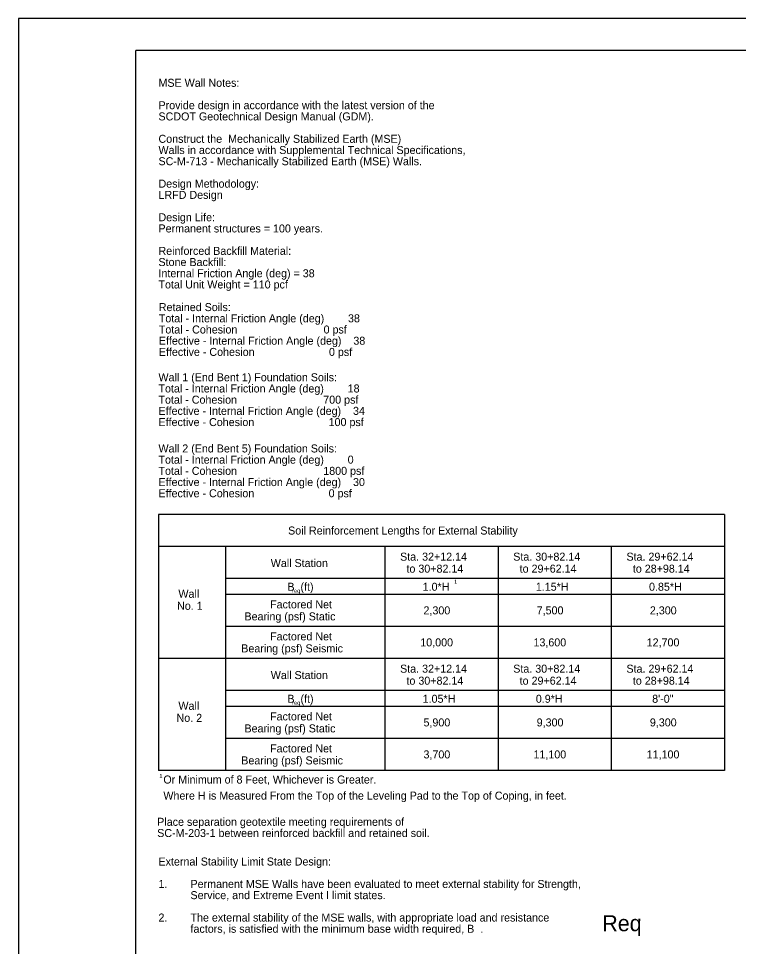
# Model space of a CAD drawing. Extents: x 96 to 240, y 601 to 689.
# Drawn here: x 95.8 to 140.8, y 631 to 689 of the extents above; entities that cross this region are included whole.
import ezdxf

# ---------------------------------------------------------------- set-up
doc = ezdxf.new("R2010")
doc.units = 0
for name, color, linetype in [('BR_BORDER LINES', 7, 'Continuous'), ('BR_TABLE LINES', 7, 'Continuous'), ('BR_TEXT', 7, 'Continuous'), ('Level 31', 7, 'Continuous')]:
    doc.layers.add(name, color=color, linetype=linetype)

msp = doc.modelspace()

# ---------------------------------------------------------------- linework, layer by layer
at = {"layer": 'BR_BORDER LINES'}
for p in [(237.837, 687.003), (103.173, 603.003)]:
    msp.add_line(p, (103.173, 687.003), dxfattribs=at)
at = {"layer": 'BR_TABLE LINES'}
for p, q in [((139.93, 658.013), (104.579, 658.013)), ((104.579, 658.013), (104.579, 642.013)), ((139.93, 658.013), (139.93, 642.013)), ((139.93, 656.013), (104.579, 656.013)), ((108.755, 656.013), (108.755, 642.013)), ((118.72, 656.013), (118.72, 642.013)), ((125.79, 656.013), (125.79, 642.013)), ((132.86, 656.013), (132.86, 642.013)), ((139.93, 654.013), (108.755, 654.013)), ((139.93, 653.013), (108.755, 653.013)), ((139.93, 651.013), (108.755, 651.013)), ((139.93, 649.013), (104.579, 649.013)), ((139.93, 647.013), (108.755, 647.013)), ((139.93, 646.013), (108.755, 646.013)), ((139.93, 644.013), (108.755, 644.013)), ((139.93, 642.013), (104.579, 642.013))]:
    msp.add_line(p, q, dxfattribs=at)
at = {"layer": 'Level 31'}
msp.add_lwpolyline([(95.84, 601.004), (239.84, 601.004), (239.84, 689.004), (95.84, 689.004)], close=True, dxfattribs=at)

# ---------------------------------------------------------------- texts
at = {"layer": 'BR_TEXT'}
for s, height, p in [('MSE Wall Notes:', 0.5, (104.579, 684.739)), ('Provide design in accordance with the latest version of the ', 0.5, (104.579, 683.339)), ('SCDOT Geotechnical Design Manual (GDM). ', 0.5, (104.579, 682.639)), ('Construct the  Mechanically Stabilized Earth (MSE) ', 0.5, (104.579, 681.239)), ('Walls in accordance with Supplemental Technical Specifications,', 0.5, (104.579, 680.539)), ('SC-M-713 - Mechanically Stabilized Earth (MSE) Walls.', 0.5, (104.579, 679.839)), ('Design Methodology:', 0.5, (104.579, 678.439)), ('LRFD Design', 0.5, (104.579, 677.739)), ('Design Life:', 0.5, (104.579, 676.339)), ('Permanent structures = 100 years.', 0.5, (104.579, 675.639)), ('Reinforced Backfill Material:', 0.5, (104.579, 674.239)), ('Stone Backfill:', 0.5, (104.579, 673.539)), ('Internal Friction Angle (deg) = 38', 0.5, (104.579, 672.839)), ('Total Unit Weight = 110 pcf', 0.5, (104.579, 672.139)), ('Retained Soils:', 0.5, (104.6, 670.724)), ('Total - Internal Friction Angle (deg)        38', 0.5, (104.6, 670.024)), ('Total - Cohesion                             0 psf', 0.5, (104.6, 669.324)), ('Effective - Internal Friction Angle (deg)    38', 0.5, (104.6, 668.624)), ('Effective - Cohesion                         0 psf', 0.5, (104.6, 667.924)), ('Wall 1 (End Bent 1) Foundation Soils:', 0.5, (104.579, 666.34)), ('Total - Internal Friction Angle (deg)        18', 0.5, (104.579, 665.64)), ('Total - Cohesion                             700 psf', 0.5, (104.579, 664.94)), ('Effective - Internal Friction Angle (deg)    34', 0.5, (104.579, 664.24)), ('Effective - Cohesion                         100 psf', 0.5, (104.579, 663.54)), ('Wall 2 (End Bent 5) Foundation Soils:', 0.5, (104.579, 661.892)), ('Total - Internal Friction Angle (deg)        0', 0.5, (104.579, 661.192)), ('Total - Cohesion                             1800 psf', 0.5, (104.579, 660.492)), ('Effective - Internal Friction Angle (deg)    30', 0.5, (104.579, 659.792)), ('Effective - Cohesion                         0 psf', 0.5, (104.579, 659.092)), ('Place separation geotextile meeting requirements of ', 0.5, (104.499, 638.562)), ('SC-M-203-1 between reinforced backfill and retained soil.', 0.5, (104.499, 637.862)), ('External Stability Limit State Design:', 0.5, (104.579, 636.081)), ('1.', 0.5, (104.579, 634.681)), ('Permanent MSE Walls have been evaluated to meet external stability for Strength,', 0.5, (106.579, 634.681)), ('Service, and Extreme Event I limit states.', 0.5, (106.579, 633.981)), ('2.', 0.5, (104.579, 632.581)), ('The external stability of the MSE walls, with appropriate load and resistance', 0.5, (106.579, 632.581)), ('          Req', 1, (128.587, 631.976)), ('factors, is satisfied with the minimum base width required, B  .', 0.5, (106.579, 631.881))]:
    msp.add_text(s, height=height, dxfattribs=at).set_placement(p)
for s, height, p in [('Soil Reinforcement Lengths for External Stability', 0.5, (112.677, 656.763)), ('Wall Station', 0.5, (111.592, 654.731)), ('Sta. 32+12.14 ', 0.5, (119.669, 655.131)), ('Sta. 30+82.14', 0.5, (126.739, 655.131)), ('Sta. 29+62.14', 0.5, (133.809, 655.131)), ('to 30+82.14', 0.5, (120.069, 654.381)), ('to 29+62.14', 0.5, (127.139, 654.381)), ('to 28+98.14', 0.5, (134.209, 654.381)), ('B  (ft)', 0.5, (112.631, 653.251)), ('1.0*H', 0.5, (121.079, 653.251)), ('1', 0.25, (123.044, 653.69)), ('1.15*H', 0.5, (128.149, 653.251)), ('0.85*H', 0.5, (135.219, 653.251)), ('Wall', 0.5, (105.824, 652.81)), ('req', 0.25, (112.933, 653.126)), ('No. 1', 0.5, (105.741, 652.06)), ('Factored Net', 0.5, (111.551, 652.149)), ('2,300', 0.5, (121.132, 651.774)), ('7,500', 0.5, (128.202, 651.774)), ('2,300', 0.5, (135.272, 651.774)), ('Bearing (psf) Static', 0.5, (109.95, 651.399)), ('Factored Net', 0.5, (111.551, 650.149)), ('10,000', 0.5, (120.932, 649.774)), ('13,600', 0.5, (128.002, 649.774)), ('12,700', 0.5, (135.072, 649.774)), ('Bearing (psf) Seismic', 0.5, (109.75, 649.399)), ('Wall Station', 0.5, (111.592, 647.731)), ('Sta. 32+12.14 ', 0.5, (119.669, 648.131)), ('Sta. 30+82.14', 0.5, (126.739, 648.131)), ('Sta. 29+62.14', 0.5, (133.809, 648.131)), ('to 30+82.14', 0.5, (120.069, 647.381)), ('to 29+62.14', 0.5, (127.139, 647.381)), ('to 28+98.14', 0.5, (134.209, 647.381)), ('B  (ft)', 0.5, (112.631, 646.251)), ('1.05*H', 0.5, (121.079, 646.251)), ('0.9*H', 0.5, (128.149, 646.251)), ('8\'-0"', 0.5, (135.416, 646.251)), ('Wall', 0.5, (105.824, 645.81)), ('req', 0.25, (112.933, 646.126)), ('No. 2', 0.5, (105.707, 645.06)), ('Factored Net', 0.5, (111.551, 645.149)), ('Bearing (psf) Static', 0.5, (109.95, 644.399)), ('5,900', 0.5, (121.132, 644.774)), ('9,300', 0.5, (128.202, 644.774)), ('9,300', 0.5, (135.272, 644.774)), ('Factored Net', 0.5, (111.551, 643.149)), ('3,700', 0.5, (121.132, 642.774)), ('11,100', 0.5, (128.002, 642.774)), ('11,100', 0.5, (135.072, 642.774)), ('Bearing (psf) Seismic', 0.5, (109.75, 642.399)), ('1', 0.25, (104.637, 641.542)), ('Or Minimum of 8 Feet, Whichever is Greater.', 0.5, (104.885, 641.204)), ('Where H is Measured From the Top of the Leveling Pad to the Top of Coping, in feet.', 0.5, (104.885, 640.2))]:
    msp.add_text(s, height=height, rotation=359.99994, dxfattribs=at).set_placement(p)

doc.saveas('drawing.dxf')
